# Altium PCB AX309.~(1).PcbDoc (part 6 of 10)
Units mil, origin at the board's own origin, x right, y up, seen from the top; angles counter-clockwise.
Board outline 5185 x 3614 mil, 4 copper layers (Top Layer, GND, Mid-Layer 1, Bottom Layer); 191 components, 352 nets, 1106 pads, 425 vias.
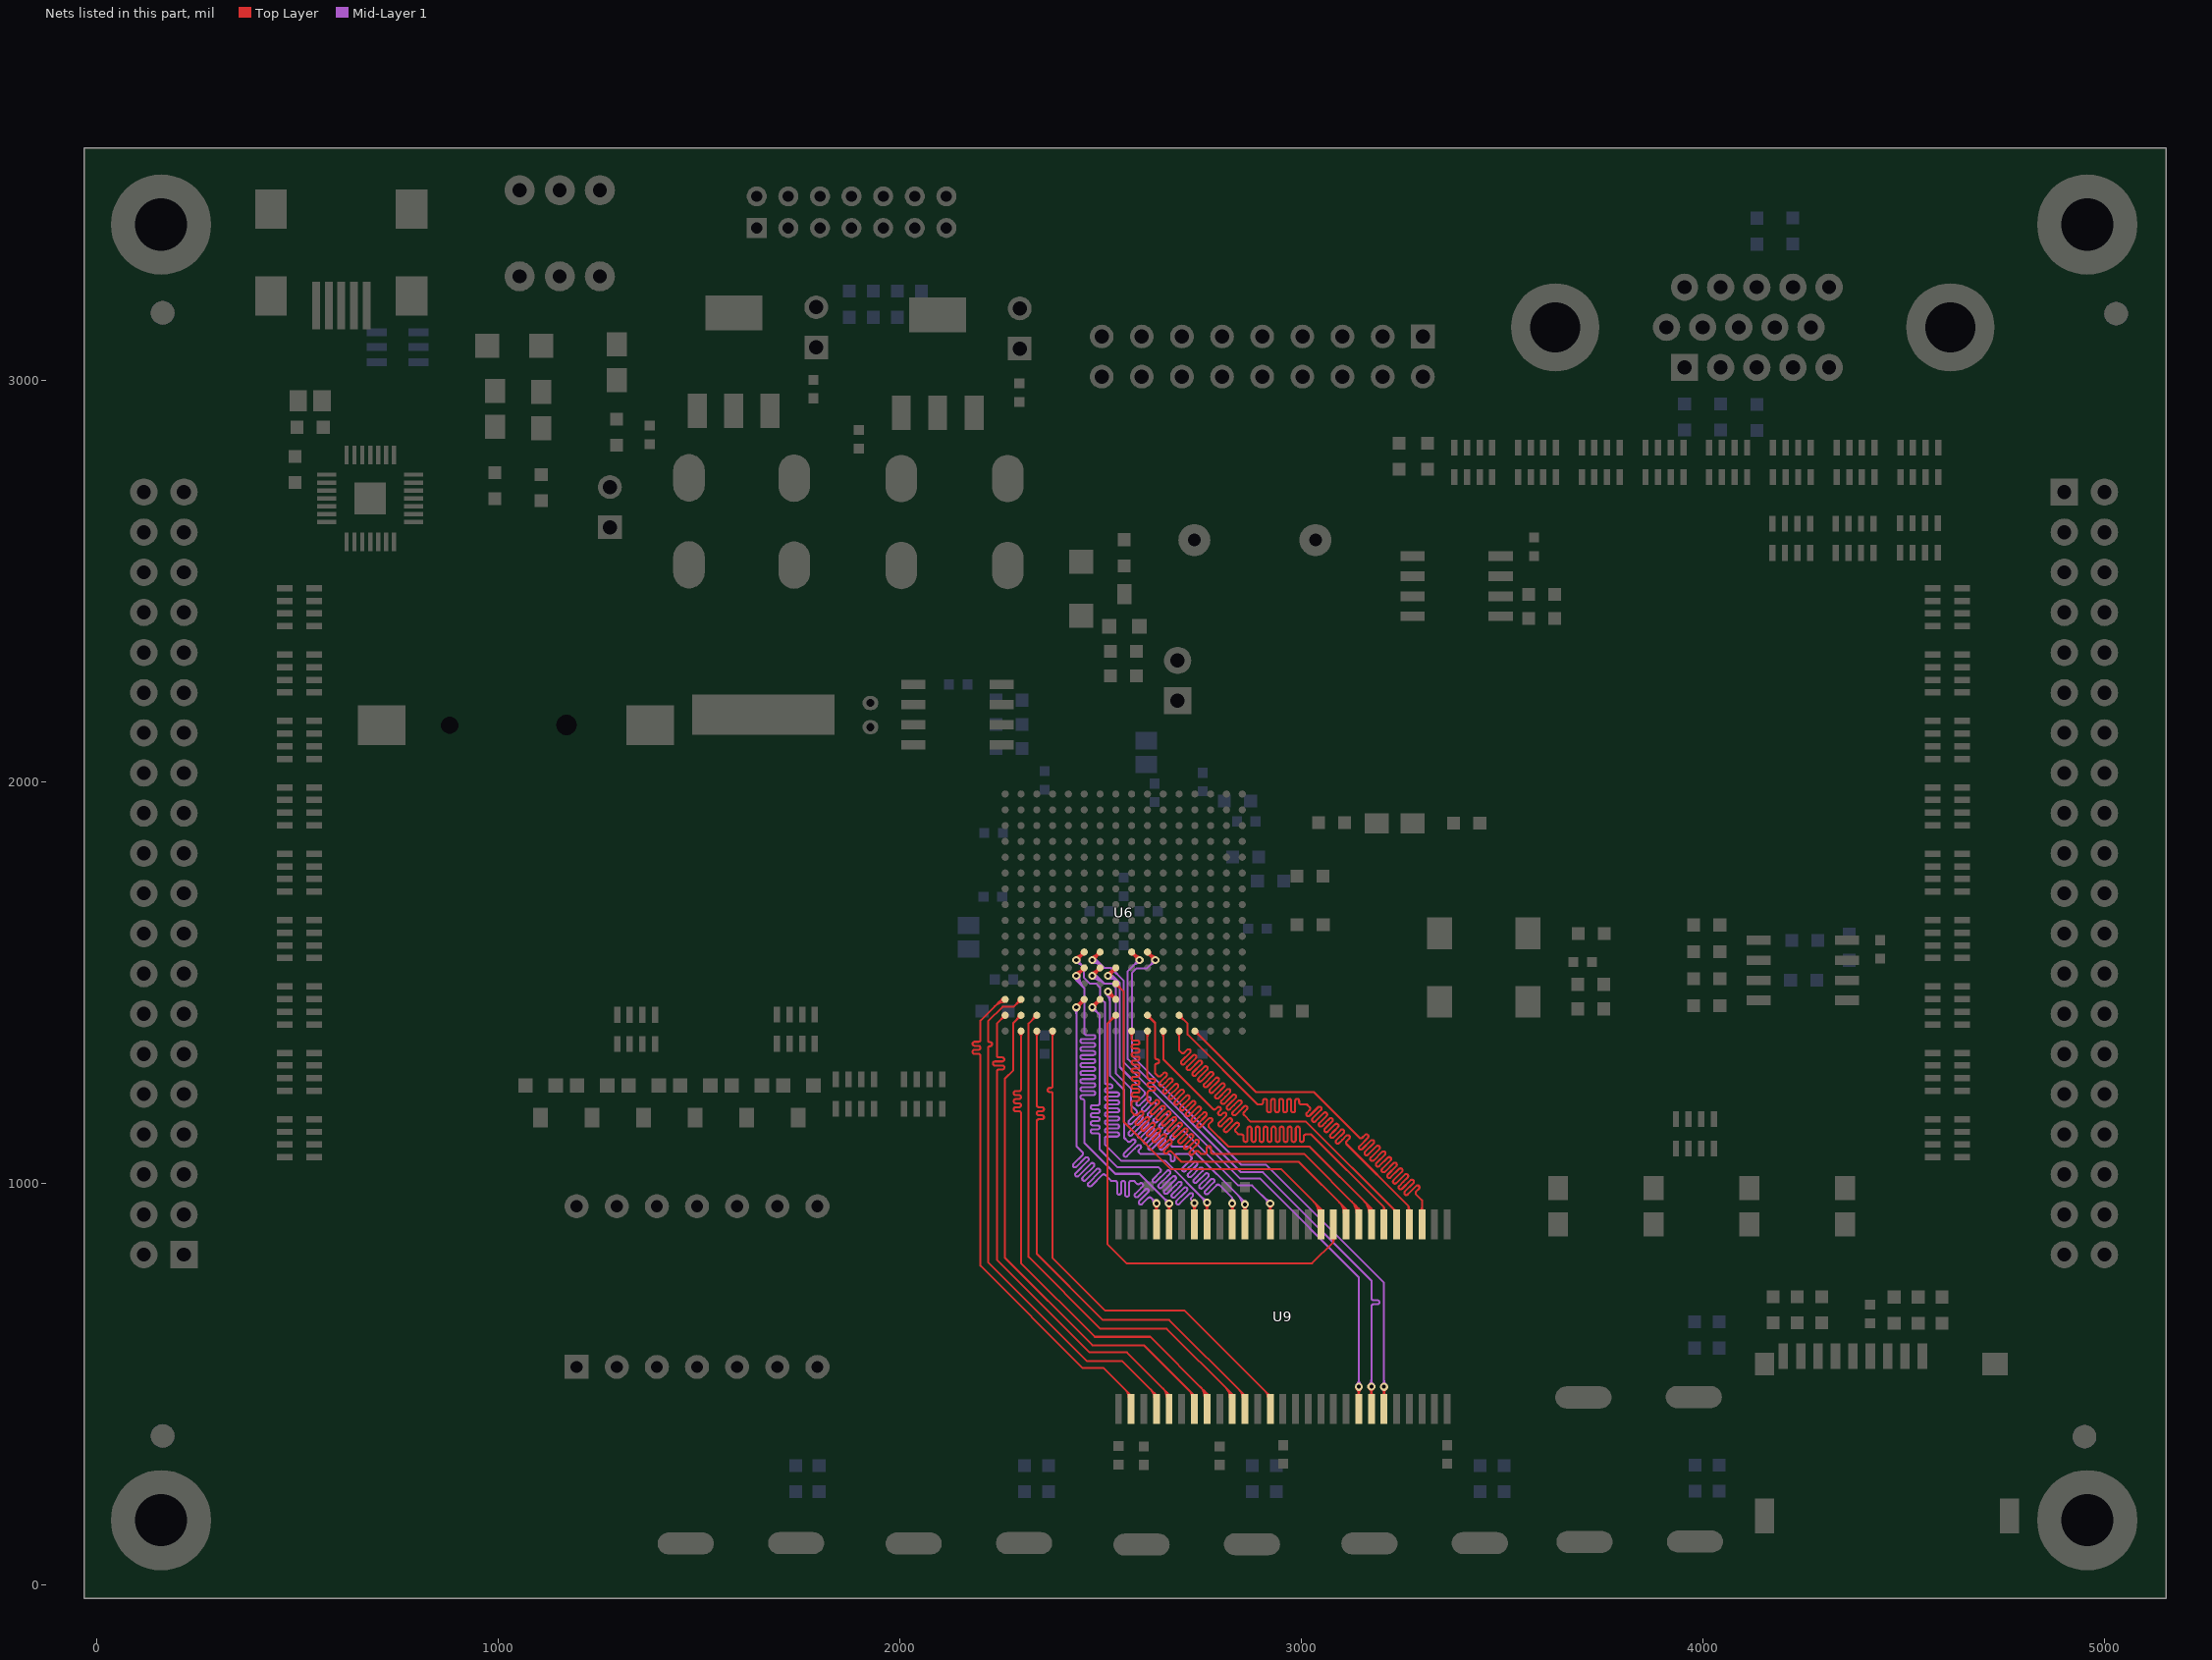
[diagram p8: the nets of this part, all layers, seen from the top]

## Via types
v1: diameter 20, hole 10, Top Layer to Bottom Layer, 328 vias
v2: diameter 30, hole 15, Top Layer to Bottom Layer, 95 vias
v3: diameter 40, hole 20, Top Layer to Bottom Layer, 2 vias

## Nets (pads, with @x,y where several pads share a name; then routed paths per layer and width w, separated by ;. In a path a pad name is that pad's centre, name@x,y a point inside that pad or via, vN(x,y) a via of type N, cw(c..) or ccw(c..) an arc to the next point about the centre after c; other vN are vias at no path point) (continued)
S_A5: U6.N1 U9.30 | length 1517.2
  Top Layer w5: U6.N1@2735.17,1372.37 cw(c2735.17,1357.02) 2746.02,1367.87 cw(c2756.87,1378.72) U6.N1@2741.52,1378.72 ; U6.N1@2735.17,1378.72 2886.89,1227 3031,1227 3145,1113 ccw(c3148.54,1116.54) 3152.07,1113 3159.06,1119.99 cw(c3162.6,1116.46) 3166.13,1119.99 cw(c3162.6,1116.46) 3166.13,1112.92 3145.08,1091.87 ccw(c3148.62,1088.33) 3145.08,1084.8 ccw(c3148.62,1088.33) 3152.15,1084.8 3173.2,1105.85 cw(c3176.74,1102.31) 3180.28,1105.85 cw(c3176.74,1102.31) 3180.28,1098.78 3159.22,1077.72 ccw(c3162.76,1074.19) 3159.22,1070.65 ccw(c3162.76,1074.19) 3166.29,1070.65 3187.35,1091.71 cw(c3190.88,1088.17) 3194.42,1091.71 cw(c3190.88,1088.17) 3194.42,1084.64 3173.36,1063.58 ccw(c3176.9,1060.05) 3173.36,1056.51 ccw(c3176.9,1060.05) 3180.43,1056.51 3201.49,1077.57 cw(c3205.02,1074.03) 3208.56,1077.57 cw(c3205.02,1074.03) 3208.56,1070.49 3187.51,1049.44 ccw(c3191.04,1045.9) 3187.51,1042.37 ccw(c3191.04,1045.9) 3194.58,1042.37 3215.63,1063.42 cw(c3219.17,1059.89) 3222.7,1063.42 cw(c3219.17,1059.89) 3222.7,1056.35 3201.65,1035.3 ccw(c3205.18,1031.76) 3201.65,1028.23 ccw(c3205.18,1031.76) 3208.72,1028.23 3229.77,1049.28 cw(c3233.31,1045.75) 3236.84,1049.28 cw(c3233.31,1045.75) 3236.84,1042.21 3215.79,1021.16 ccw(c3219.33,1017.62) 3215.79,1014.08 ccw(c3219.33,1017.62) 3222.86,1014.08 3243.92,1035.14 cw(c3247.45,1031.6) 3250.99,1035.14 cw(c3247.45,1031.6) 3250.99,1028.07 3229.93,1007.01 ccw(c3233.47,1003.48) 3229.93,999.94 ccw(c3233.47,1003.48) 3237,999.94 3258.06,1021 cw(c3261.59,1017.46) 3265.13,1021 cw(c3261.59,1017.46) 3265.13,1013.93 3254.6,1003.4 3244.07,992.87 ccw(c3247.61,989.34) 3244.07,985.8 ccw(c3247.61,989.34) 3251.15,985.8 3272.2,1006.85 cw(c3275.74,1003.32) 3279.27,1006.85 cw(c3275.74,1003.32) 3279.27,999.78 3258.22,978.73 ccw(c3261.75,975.19) 3258.22,971.66 ccw(c3261.75,975.19) 3265.29,971.66 3286.34,992.71 cw(c3289.88,989.18) 3293.41,992.71 cw(c3289.88,989.18) 3293.41,985.64 3286.42,978.65 ccw(c3289.96,975.11) 3286.42,971.58 3300.91,957.09 U9.30@3300.91,897 ; U9.30@3296.66,930.24 ccw(c3286.42,940.49) 3300.91,940.49 ccw(c3315.39,940.49) U9.30@3305.15,930.24
S_A6: U6.M2 U9.31 | length 1514.3
  Top Layer w5: U6.M2@2695.8,1411.74 cw(c2695.8,1396.39) 2706.65,1407.24 cw(c2717.5,1418.09) U6.M2@2702.15,1418.09 ; U6.M2@2695.8,1418.09 2717,1396.89 2717,1370 2891,1196 2900,1196 ccw(c2900,1201) 2905,1201 2905,1204.8 cw(c2910,1204.8) 2910,1209.8 cw(c2910,1204.8) 2915,1204.8 2915,1181.2 ccw(c2920,1181.2) 2920,1176.2 ccw(c2920,1181.2) 2925,1181.2 2925,1204.8 cw(c2930,1204.8) 2930,1209.8 cw(c2930,1204.8) 2935,1204.8 2935,1181.2 ccw(c2940,1181.2) 2940,1176.2 ccw(c2940,1181.2) 2945,1181.2 2945,1204.8 cw(c2950,1204.8) 2950,1209.8 cw(c2950,1204.8) 2955,1204.8 2955,1181.2 ccw(c2960,1181.2) 2960,1176.2 ccw(c2960,1181.2) 2965,1181.2 2965,1204.8 cw(c2970,1204.8) 2970,1209.8 cw(c2970,1204.8) 2975,1204.8 2975,1181.2 ccw(c2980,1181.2) 2980,1176.2 ccw(c2980,1181.2) 2985,1181.2 2985,1204.8 cw(c2990,1204.8) 2990,1209.8 cw(c2990,1204.8) 2995,1204.8 2995,1201 ccw(c3000,1201) 3000,1196 3014,1196 3021.07,1188.93 cw(c3017.54,1185.39) 3021.07,1181.86 3014.14,1174.93 ccw(c3017.68,1171.39) 3014.14,1167.86 ccw(c3017.68,1171.39) 3021.21,1167.86 3042.14,1188.79 cw(c3045.68,1185.25) 3049.22,1188.79 cw(c3045.68,1185.25) 3049.22,1181.72 3028.28,1160.78 ccw(c3031.82,1157.25) 3028.28,1153.71 ccw(c3031.82,1157.25) 3035.35,1153.71 3056.29,1174.65 cw(c3059.82,1171.11) 3063.36,1174.65 cw(c3059.82,1171.11) 3063.36,1167.58 3045.14,1149.35 ccw(c3048.67,1145.82) 3045.14,1142.28 ccw(c3048.67,1145.82) 3052.21,1142.28 3059.96,1150.04 3070.43,1160.51 cw(c3073.96,1156.97) 3077.5,1160.5 cw(c3073.96,1156.97) 3077.5,1153.43 3059.28,1135.21 ccw(c3062.81,1131.68) 3059.28,1128.14 ccw(c3062.81,1131.68) 3066.35,1128.14 3084.57,1146.36 cw(c3088.11,1142.83) 3091.64,1146.36 cw(c3088.11,1142.83) 3091.64,1139.29 3081.18,1128.82 3073.42,1121.07 ccw(c3076.96,1117.53) 3073.42,1114 ccw(c3076.96,1117.53) 3080.49,1114 3098.71,1132.22 cw(c3102.25,1128.69) 3105.78,1132.22 cw(c3102.25,1128.69) 3105.78,1125.15 3087.56,1106.93 ccw(c3091.1,1103.39) 3087.56,1099.86 ccw(c3091.1,1103.39) 3094.63,1099.86 3102.39,1107.61 3112.86,1118.08 cw(c3116.39,1114.54) 3119.93,1118.08 cw(c3116.39,1114.54) 3119.93,1111.01 3112.99,1104.08 ccw(c3116.53,1100.54) 3112.99,1097.01 3267.5,942.5 ; U9.31@3265.17,930.24 ccw(c3259.53,935.88) 3267.5,935.88 ; U9.31@3267.5,898.91 3267.5,942.5 ; U9.31@3273.17,930.68 cw(c3282.66,942.5) 3267.5,942.5
S_A7: U6.M1 U9.32 | length 1542
  Top Layer w5: U6.M1@2691.3,1374.23 cw(c2680.45,1363.37) 2695.8,1363.37 cw(c2711.15,1363.37) U6.M1@2700.29,1374.23 ; U6.M1@2695.8,1378.72 2695.8,1331.2 2702,1325 ccw(c2705.54,1328.54) 2709.07,1325 2716.1,1332.03 cw(c2719.64,1328.5) 2723.17,1332.03 cw(c2719.64,1328.5) 2723.17,1324.96 2702.04,1303.83 ccw(c2705.57,1300.29) 2702.04,1296.75 ccw(c2705.57,1300.29) 2709.11,1296.75 2730.25,1317.89 cw(c2733.78,1314.35) 2737.32,1317.89 cw(c2733.78,1314.35) 2737.32,1310.82 2716.18,1289.68 ccw(c2719.72,1286.15) 2716.18,1282.61 ccw(c2719.72,1286.15) 2723.25,1282.61 2744.39,1303.75 cw(c2747.92,1300.21) 2751.46,1303.75 cw(c2747.92,1300.21) 2751.46,1296.68 2730.32,1275.54 ccw(c2733.86,1272.01) 2730.32,1268.47 ccw(c2733.86,1272.01) 2737.39,1268.47 2758.53,1289.61 cw(c2762.06,1286.07) 2765.6,1289.61 cw(c2762.06,1286.07) 2765.6,1282.53 2744.47,1261.4 ccw(c2748,1257.86) 2744.47,1254.33 ccw(c2748,1257.86) 2751.54,1254.33 2772.67,1275.46 cw(c2776.21,1271.93) 2779.74,1275.46 cw(c2776.21,1271.93) 2779.74,1268.39 2758.61,1247.26 ccw(c2762.14,1243.72) 2758.61,1240.19 ccw(c2762.14,1243.72) 2765.68,1240.19 2786.81,1261.32 cw(c2790.35,1257.79) 2793.88,1261.32 cw(c2790.35,1257.79) 2793.88,1254.25 2772.75,1233.12 ccw(c2776.29,1229.58) 2772.75,1226.04 ccw(c2776.29,1229.58) 2779.82,1226.04 2800.96,1247.18 cw(c2804.49,1243.64) 2808.03,1247.18 cw(c2804.49,1243.64) 2808.03,1240.11 2786.89,1218.97 ccw(c2790.43,1215.44) 2786.89,1211.9 ccw(c2790.43,1215.44) 2793.96,1211.9 2815.1,1233.04 cw(c2818.63,1229.5) 2822.17,1233.04 cw(c2818.63,1229.5) 2822.17,1225.97 2811.6,1215.4 2801.64,1205.43 ccw(c2805.17,1201.9) 2801.64,1198.36 ccw(c2805.17,1201.9) 2808.71,1198.36 2818.67,1208.33 2829.24,1218.89 cw(c2832.78,1215.36) 2836.31,1218.89 cw(c2832.78,1215.36) 2836.31,1211.82 2825.74,1201.26 2815.78,1191.29 ccw(c2819.32,1187.76) 2815.78,1184.22 ccw(c2819.32,1187.76) 2822.85,1184.22 2832.81,1194.19 2843.38,1204.75 cw(c2846.92,1201.22) 2850.45,1204.75 cw(c2846.92,1201.22) 2850.45,1197.68 2839.89,1187.11 2829.92,1177.15 ccw(c2833.46,1173.61) 2829.92,1170.08 ccw(c2833.46,1173.61) 2836.99,1170.08 2846.96,1180.04 2857.52,1190.61 cw(c2861.06,1187.07) 2864.6,1190.61 cw(c2861.06,1187.07) 2864.6,1183.54 2857.56,1176.51 ccw(c2861.1,1172.97) 2857.56,1169.44 2874,1153 3012,1153 U9.32@3237.91,927.09 ; 3226.9,938.1 cw(c3214.8,926) U9.32@3231.91,926 ; 3229.53,935.47 ccw(c3237.91,943.86) U9.32@3237.91,932
S_A8: U6.L1 U9.33 | length 1539.8
  Top Layer w5: U6.L1@2651.93,1374.23 cw(c2641.08,1363.37) 2656.43,1363.37 cw(c2671.78,1363.37) U6.L1@2660.92,1374.23 ; U6.L1@2656.43,1378.72 2656.43,1308.57 2780.36,1184.64 ccw(c2783.9,1188.18) 2787.43,1184.64 2791.14,1188.35 cw(c2794.68,1184.81) 2798.21,1188.35 cw(c2794.68,1184.81) 2798.21,1181.28 2794.5,1177.57 ccw(c2798.04,1174.03) 2794.5,1170.5 ccw(c2798.04,1174.03) 2801.57,1170.5 2805.28,1174.21 cw(c2808.82,1170.67) 2812.35,1174.21 cw(c2808.82,1170.67) 2812.35,1167.14 2805.11,1159.89 2794.76,1149.54 ccw(c2798.29,1146) 2794.76,1142.47 ccw(c2798.29,1146) 2801.83,1142.47 2819.43,1160.06 cw(c2822.96,1156.53) 2826.5,1160.06 cw(c2822.96,1156.53) 2826.5,1152.99 2819.25,1145.75 2808.9,1135.4 ccw(c2812.43,1131.86) 2808.9,1128.32 ccw(c2812.43,1131.86) 2815.97,1128.32 2836.68,1149.03 cw(c2840.21,1145.5) 2843.75,1149.03 cw(c2840.21,1145.5) 2843.75,1141.96 2836.93,1135.14 ccw(c2840.46,1131.61) 2836.93,1128.07 2844,1121 2851.39,1121 cw(c2851.39,1116) 2856.39,1116 2856.39,1107.36 ccw(c2861.39,1107.36) 2861.39,1102.36 ccw(c2861.39,1107.36) 2866.39,1107.36 2866.39,1135.64 cw(c2871.39,1135.64) 2871.39,1140.64 cw(c2871.39,1135.64) 2876.39,1135.64 2876.39,1107.36 ccw(c2881.39,1107.36) 2881.39,1102.36 ccw(c2881.39,1107.36) 2886.39,1107.36 2886.39,1135.64 cw(c2891.39,1135.64) 2891.39,1140.64 cw(c2891.39,1135.64) 2896.39,1135.64 2896.39,1107.36 ccw(c2901.39,1107.36) 2901.39,1102.36 ccw(c2901.39,1107.36) 2906.39,1107.36 2906.39,1135.64 cw(c2911.39,1135.64) 2911.39,1140.64 cw(c2911.39,1135.64) 2916.39,1135.64 2916.39,1107.36 ccw(c2921.39,1107.36) 2921.39,1102.36 ccw(c2921.39,1107.36) 2926.39,1107.36 2926.39,1135.64 cw(c2931.39,1135.64) 2931.39,1140.64 cw(c2931.39,1135.64) 2936.39,1135.64 2936.39,1107.36 ccw(c2941.39,1107.36) 2941.39,1102.36 ccw(c2941.39,1107.36) 2946.39,1107.36 2946.39,1135.64 cw(c2951.39,1135.64) 2951.39,1140.64 cw(c2951.39,1135.64) 2956.39,1135.64 2956.39,1107.36 ccw(c2961.39,1107.36) 2961.39,1102.36 ccw(c2961.39,1107.36) 2966.39,1107.36 2966.39,1135.64 cw(c2971.39,1135.64) 2971.39,1140.64 cw(c2971.39,1135.64) 2976.39,1135.64 2976.39,1107.36 ccw(c2981.39,1107.36) 2981.39,1102.36 ccw(c2981.39,1107.36) 2986.39,1107.36 2986.39,1135.64 cw(c2991.39,1135.64) 2991.39,1140.64 cw(c2991.39,1135.64) 2996.39,1135.64 2996.39,1107.36 ccw(c3001.39,1107.36) 3001.39,1102.36 ccw(c3001.39,1107.36) 3006.39,1107.36 3006.39,1116 cw(c3011.39,1116) 3011.39,1121 3025,1121 3206.42,939.58 ; U9.33@3202.38,930.44 ccw(c3194.04,939.58) 3206.42,939.58 ; U9.33@3206.42,897 3206.42,939.58 ; U9.33@3210.46,930.44 cw(c3218.79,939.58) 3206.42,939.58
S_A9: U6.K2 U9.34 | length 1576.9
  Top Layer w5: U6.K2@2617.06,1411.74 cw(c2617.06,1396.39) 2627.91,1407.24 cw(c2638.76,1418.09) U6.K2@2623.41,1418.09 ; U6.K2@2617.06,1418.09 2636,1399.15 2636,1313 ccw(c2641,1313) 2641,1308 2641.33,1308 cw(c2641.33,1303) 2646.33,1303 cw(c2641.33,1303) 2641.33,1298 2641,1298 ccw(c2641,1293) 2636,1293 2636,1274 2643.07,1266.93 ccw(c2646.61,1270.46) 2650.14,1266.93 2657.14,1273.93 cw(c2660.68,1270.39) 2664.21,1273.93 cw(c2660.68,1270.39) 2664.21,1266.86 2653.68,1256.32 2647.22,1249.87 ccw(c2650.76,1246.33) 2647.22,1242.8 ccw(c2650.76,1246.33) 2654.3,1242.8 2660.75,1249.25 2671.28,1259.79 cw(c2674.82,1256.25) 2678.35,1259.79 cw(c2674.82,1256.25) 2678.35,1252.72 2657.28,1231.65 ccw(c2660.82,1228.11) 2657.28,1224.57 ccw(c2660.82,1228.11) 2664.36,1224.57 2685.43,1245.64 cw(c2688.96,1242.11) 2692.5,1245.64 cw(c2688.96,1242.11) 2692.5,1238.57 2671.43,1217.5 ccw(c2674.96,1213.97) 2671.43,1210.43 ccw(c2674.96,1213.97) 2678.5,1210.43 2699.57,1231.5 cw(c2703.1,1227.97) 2706.64,1231.5 cw(c2703.1,1227.97) 2706.64,1224.43 2685.57,1203.36 ccw(c2689.1,1199.83) 2685.57,1196.29 ccw(c2689.1,1199.83) 2692.64,1196.29 2713.71,1217.36 cw(c2717.25,1213.82) 2720.78,1217.36 cw(c2717.25,1213.82) 2720.78,1210.29 2699.71,1189.22 ccw(c2703.25,1185.68) 2699.71,1182.15 ccw(c2703.25,1185.68) 2706.78,1182.15 2727.85,1203.22 cw(c2731.39,1199.68) 2734.92,1203.22 cw(c2731.39,1199.68) 2734.92,1196.15 2713.85,1175.08 ccw(c2717.39,1171.54) 2713.85,1168.01 ccw(c2717.39,1171.54) 2720.92,1168.01 2741.99,1189.08 cw(c2745.53,1185.54) 2749.07,1189.08 cw(c2745.53,1185.54) 2749.07,1182 2728,1160.93 ccw(c2731.53,1157.4) 2728,1153.86 ccw(c2731.53,1157.4) 2735.07,1153.86 2745.6,1164.4 2756.14,1174.93 cw(c2759.67,1171.4) 2763.21,1174.93 cw(c2759.67,1171.4) 2763.21,1167.86 2742.14,1146.79 ccw(c2745.67,1143.26) 2742.14,1139.72 ccw(c2745.67,1143.26) 2749.21,1139.72 2770.28,1160.79 cw(c2773.81,1157.26) 2777.35,1160.79 cw(c2773.81,1157.26) 2777.35,1153.72 2770.35,1146.72 ccw(c2773.89,1143.19) 2770.35,1139.65 2819,1091 3021,1091 3175,937 ; 3156.98,955.02 cw(c3127.96,926) U9.34@3169,926 ; 3165.51,946.49 cw(c3145.03,926) U9.34@3174,926 ; U9.34@3171.75,931.04 ccw(c3167.92,937) 3175,937 ; 3174.05,937.95 cw(c3162.1,926) U9.34@3179,926 ; U9.34@3175,897 3175,937 ; U9.34@3178.25,931.04 cw(c3182.08,937) 3175,937
S_A10: U6.K6 U9.22 | length 1742.1
  Top Layer w5: U6.K6@2617.06,1569.22 cw(c2617.06,1553.87) 2627.91,1564.72 cw(c2638.76,1575.57) U6.K6@2623.41,1575.57 ; U6.K6@2617.06,1575.57 v1(2636.74,1555.89) ; U6.K6@2619.41,1569.63 cw(c2609.33,1552.17) v1@2629.31,1554.88 ; U6.K6@2623,1573.22 ccw(c2640.46,1583.3) v1@2637.75,1563.32 ; 2626.29,1565.65 cw(c2622.84,1559.67) v1@2629.5,1557.86 ; 2626.98,1566.34 ccw(c2632.96,1569.79) v1@2634.77,1563.13 ; 2628.1,1564.39 ccw(c2638.73,1570.53) v1@2637.08,1558.37 ; 2628.24,1564.53 cw(c2622.1,1553.9) v1@2634.26,1555.55 ; v1@2629.24,1555.89 ccw(c2611.13,1555.89) 2623.94,1568.69 ccw(c2636.74,1581.5) v1@2636.74,1563.39 ; v1@3201.11,487.11 cw(c3188.31,474.31) 3206.42,474.31 cw(c3224.52,474.31) v1@3211.72,487.11 ; U9.22@3202.17,470.24 ccw(c3191.93,480.49) 3206.42,480.49 ccw(c3220.9,480.49) U9.22@3210.66,470.24 ; U9.22@3206.42,437 v1(3206.42,492.42) ; v1@2629.5,1557.83 ccw(c2622.67,1559.66) 2628.79,1563.19 cw(c2622.67,1559.66) v1@2629.5,1557.83 ; 2629.44,1563.84 ccw(c2632.97,1569.96) 2634.8,1563.13 cw(c2632.97,1569.96) 2629.44,1563.84
  Mid-Layer 1 w5: v1@2629.24,1555.89 cw(c2611.13,1555.89) 2623.94,1543.09 cw(c2636.74,1530.28) v1@2636.74,1548.39 ; v1(2636.74,1555.89) 2615.85,1535 2590,1535 2579,1524 2579,1317 2850,1046 2912,1046 3206.42,751.58 v1(3206.42,492.42) ; v1@3201.11,497.72 ccw(c3188.31,510.52) 3206.42,510.52 ccw(c3224.52,510.52) v1@3211.72,497.72
S_A11: U6.K1 U9.35 | length 1573.4
  Top Layer w5: U6.K1@2612.56,1374.23 cw(c2601.7,1363.37) 2617.06,1363.37 cw(c2632.41,1363.37) U6.K1@2621.55,1374.23 ; U6.K1@2617.06,1378.72 2617.06,1265 ccw(c2622.06,1265) 2622.06,1260 2631.59,1260 cw(c2631.59,1255) 2636.59,1255 cw(c2631.59,1255) 2631.59,1250 2622.06,1250 ccw(c2622.06,1245) 2617.06,1245 ccw(c2622.06,1245) 2622.06,1240 2631.59,1240 cw(c2631.59,1235) 2636.59,1235 cw(c2631.59,1235) 2631.59,1230 2622.06,1230 ccw(c2622.06,1225) 2617.06,1225 2617.06,1205.94 2624.13,1198.87 ccw(c2627.66,1202.41) 2631.2,1198.87 2637.94,1205.62 cw(c2641.48,1202.08) 2645.01,1205.62 cw(c2641.48,1202.08) 2645.01,1198.55 2634.73,1188.27 2626.13,1179.66 ccw(c2629.66,1176.13) 2626.13,1172.59 ccw(c2629.66,1176.13) 2633.2,1172.59 2641.8,1181.2 2652.08,1191.48 cw(c2655.62,1187.94) 2659.16,1191.48 cw(c2655.62,1187.94) 2659.16,1184.41 2640.27,1165.52 ccw(c2643.81,1161.99) 2640.27,1158.45 ccw(c2643.81,1161.99) 2647.34,1158.45 2655.95,1167.05 2666.23,1177.33 cw(c2669.76,1173.8) 2673.3,1177.33 cw(c2669.76,1173.8) 2673.3,1170.26 2663.02,1159.98 2654.41,1151.38 ccw(c2657.95,1147.84) 2654.41,1144.31 ccw(c2657.95,1147.84) 2661.48,1144.31 2670.09,1152.91 2680.37,1163.19 cw(c2683.9,1159.66) 2687.44,1163.19 cw(c2683.9,1159.66) 2687.44,1156.12 2677.16,1145.84 2668.56,1137.24 ccw(c2672.09,1133.7) 2668.56,1130.17 ccw(c2672.09,1133.7) 2675.63,1130.17 2684.23,1138.77 2694.51,1149.05 cw(c2698.05,1145.52) 2701.58,1149.05 cw(c2698.05,1145.52) 2701.58,1141.98 2691.3,1131.7 2682.7,1123.09 ccw(c2686.23,1119.56) 2682.7,1116.02 ccw(c2686.23,1119.56) 2689.77,1116.02 2698.37,1124.63 2708.65,1134.91 cw(c2712.19,1131.37) 2715.72,1134.91 cw(c2712.19,1131.37) 2715.72,1127.84 2695.16,1107.28 ccw(c2698.7,1103.74) 2695.16,1100.2 ccw(c2698.7,1103.74) 2702.23,1100.2 2722.8,1120.77 cw(c2726.33,1117.23) 2729.87,1120.77 cw(c2726.33,1117.23) 2729.87,1113.7 2709.3,1093.13 ccw(c2712.84,1089.6) 2709.3,1086.06 ccw(c2712.84,1089.6) 2716.38,1086.06 2726.66,1096.34 2736.94,1106.62 cw(c2740.47,1103.09) 2744.01,1106.62 cw(c2740.47,1103.09) 2744.01,1099.55 2723.45,1078.99 ccw(c2726.98,1075.46) 2723.45,1071.92 ccw(c2726.98,1075.46) 2730.52,1071.92 2737.26,1078.67 cw(c2740.8,1075.13) 2744.33,1078.67 2750,1073 2760,1073 ccw(c2760,1078) 2765,1078 2765,1087.54 cw(c2770,1087.54) 2770,1092.54 cw(c2770,1087.54) 2775,1087.54 2775,1078 ccw(c2780,1078) 2780,1073 3007,1073 3143.43,936.57 ; 3125.71,954.29 cw(c3097.41,926) U9.35@3137.43,926 ; 3134.24,945.76 cw(c3114.48,926) U9.35@3142.43,926 ; U9.35@3140.35,931.15 ccw(c3137.11,936.57) 3143.43,936.57 ; 3142.78,937.22 cw(c3131.55,926) U9.35@3147.43,926 ; U9.35@3143.43,897 3143.43,936.57 ; U9.35@3146.5,931.15 cw(c3149.74,936.57) 3143.43,936.57
S_A12: U6.J1 U9.36 | length 1560.2
  Top Layer w5: U6.J1@2573.19,1374.23 cw(c2562.33,1363.37) 2577.68,1363.37 cw(c2593.04,1363.37) U6.J1@2582.18,1374.23 ; U6.J1@2577.68,1378.72 2577.68,1360 ccw(c2582.68,1360) 2582.68,1355 2592.28,1355 cw(c2592.28,1350) 2597.28,1350 cw(c2592.28,1350) 2592.28,1345 2582.68,1345 ccw(c2582.68,1340) 2577.68,1340 ccw(c2582.68,1340) 2582.68,1335 2592.28,1335 cw(c2592.28,1330) 2597.28,1330 cw(c2592.28,1330) 2592.28,1325 2582.68,1325 ccw(c2582.68,1320) 2577.68,1320 ccw(c2582.68,1320) 2582.68,1315 2592.28,1315 cw(c2592.28,1310) 2597.28,1310 cw(c2592.28,1310) 2592.28,1305 2582.68,1305 ccw(c2582.68,1300) 2577.68,1300 ccw(c2582.68,1300) 2582.68,1295 2592.28,1295 cw(c2592.28,1290) 2597.28,1290 cw(c2592.28,1290) 2592.28,1285 2582.68,1285 ccw(c2582.68,1280) 2577.68,1280 ccw(c2582.68,1280) 2582.68,1275 2592.28,1275 cw(c2592.28,1270) 2597.28,1270 cw(c2592.28,1270) 2592.28,1265 2582.68,1265 ccw(c2582.68,1260) 2577.68,1260 ccw(c2582.68,1260) 2582.68,1255 2592.28,1255 cw(c2592.28,1250) 2597.28,1250 cw(c2592.28,1250) 2592.28,1245 2582.68,1245 ccw(c2582.68,1240) 2577.68,1240 ccw(c2582.68,1240) 2582.68,1235 2592.28,1235 cw(c2592.28,1230) 2597.28,1230 cw(c2592.28,1230) 2592.28,1225 2582.68,1225 ccw(c2582.68,1220) 2577.68,1220 ccw(c2582.68,1220) 2582.68,1215 2592.28,1215 cw(c2592.28,1210) 2597.28,1210 cw(c2592.28,1210) 2592.28,1205 2582.68,1205 ccw(c2582.68,1200) 2577.68,1200 2577.68,1177.32 2584.76,1170.24 ccw(c2588.29,1173.78) 2591.83,1170.24 2598.61,1177.03 cw(c2602.15,1173.49) 2605.68,1177.03 cw(c2602.15,1173.49) 2605.68,1169.96 2595.36,1159.64 2588.75,1153.03 ccw(c2592.29,1149.49) 2588.75,1145.96 ccw(c2592.29,1149.49) 2595.83,1145.96 2602.43,1152.57 2612.75,1162.89 cw(c2616.29,1159.35) 2619.83,1162.89 cw(c2616.29,1159.35) 2619.83,1155.82 2602.9,1138.89 ccw(c2606.43,1135.35) 2602.9,1131.82 ccw(c2606.43,1135.35) 2609.97,1131.82 2616.58,1138.42 2626.9,1148.74 cw(c2630.43,1145.21) 2633.97,1148.74 cw(c2630.43,1145.21) 2633.97,1141.67 2623.65,1131.35 2617.04,1124.74 ccw(c2620.57,1121.21) 2617.04,1117.67 ccw(c2620.57,1121.21) 2624.11,1117.67 2641.04,1134.6 cw(c2644.57,1131.07) 2648.11,1134.6 cw(c2644.57,1131.07) 2648.11,1127.53 2637.79,1117.21 2631.18,1110.6 ccw(c2634.72,1107.07) 2631.18,1103.53 ccw(c2634.72,1107.07) 2638.25,1103.53 2644.86,1110.14 2655.18,1120.46 cw(c2658.72,1116.92) 2662.25,1120.46 cw(c2658.72,1116.92) 2662.25,1113.39 2645.32,1096.46 ccw(c2648.86,1092.92) 2645.32,1089.39 ccw(c2648.86,1092.92) 2652.39,1089.39 2659,1096 2669.32,1106.32 cw(c2672.86,1102.78) 2676.39,1106.32 cw(c2672.86,1102.78) 2676.39,1099.25 2666.07,1088.93 2659.47,1082.32 ccw(c2663,1078.78) 2659.47,1075.25 ccw(c2663,1078.78) 2666.54,1075.25 2669.61,1078.32 cw(c2673.14,1074.78) 2676.68,1078.32 2702,1053 2993.93,1053 3111.93,935 ; 3095.32,951.61 cw(c3069.72,926) U9.36@3105.93,926 ; 3103.86,943.07 cw(c3086.79,926) U9.36@3110.93,926 ; U9.36@3109.62,931.54 ccw(c3108.18,935) 3111.93,935 ; U9.36@3111.93,897 3111.93,935 ; 3112.39,934.54 cw(c3103.86,926) U9.36@3115.93,926 ; U9.36@3114.24,931.54 cw(c3115.68,935) 3111.93,935
S_BA0: U6.G6 U9.20 | length 1782.8
  Top Layer w5: v1@2478.25,1563.32 ccw(c2475.54,1583.3) U6.G6@2493,1573.22 ; v1@2478.92,1558.37 ccw(c2477.27,1570.53) 2487.9,1564.39 ; v1(2479.26,1555.89) U6.G6@2498.94,1575.57 ; v1@2479.26,1563.39 ccw(c2479.26,1581.5) 2492.06,1568.69 ccw(c2504.87,1555.89) v1@2486.76,1555.89 ; v1@2481.23,1563.13 ccw(c2483.04,1569.79) 2489.02,1566.34 ; v1@2481.74,1555.55 cw(c2493.9,1553.9) 2487.76,1564.53 ; v1@2486.69,1554.88 cw(c2506.67,1552.17) U6.G6@2496.59,1569.63 ; 2489.71,1565.65 ccw(c2493.16,1559.67) v1@2486.5,1557.86 ; U6.G6@2492.59,1575.57 cw(c2477.24,1575.57) 2488.09,1564.72 cw(c2498.94,1553.87) U6.G6@2498.94,1569.22 ; v1@3138.12,487.12 cw(c3125.32,474.32) 3143.43,474.32 cw(c3161.53,474.32) v1@3148.73,487.12 ; U9.20@3139.18,470.24 ccw(c3128.94,480.49) 3143.43,480.49 ccw(c3157.91,480.49) U9.20@3147.67,470.24 ; U9.20@3143.43,437 v1(3143.43,492.43) ; v1@2486.5,1557.83 cw(c2493.33,1559.66) 2487.21,1563.19 ccw(c2493.33,1559.66) v1@2486.5,1557.83 ; v1@2481.2,1563.13 ccw(c2483.03,1569.96) 2486.56,1563.84 cw(c2483.03,1569.96) v1@2481.2,1563.13
  Mid-Layer 1 w5: v1@2479.22,1558.39 cw(c2479.54,1538.91) 2493.32,1552.68 ; v1(2479.26,1555.89) 2490.11,1555.89 ; v1@2479.3,1553.39 cw(c2479.81,1522.49) 2501.66,1544.34 ; v1@2479.38,1548.39 cw(c2480.08,1506.08) 2510,1536 ; v1@2486.27,1553.24 cw(c2490.11,1551.79) 2490.11,1555.89 ; v1@2486.27,1558.54 ccw(c2490.11,1559.99) 2490.11,1555.89 ; v1@3138.12,497.73 ccw(c3125.32,510.53) 3143.43,510.53 ccw(c3161.53,510.53) v1@3148.73,497.73 ; v1(3143.43,492.43) 3143.43,765.57 2898,1011 2848,1011 2558,1301 2558,1504 2526,1536 2510,1536 ; 2490.11,1555.89 2510,1536
S_BA1: U6.J6 U9.21 | length 1734.6
  Top Layer w5: U6.J6@2577.68,1569.22 cw(c2577.68,1553.87) 2588.54,1564.72 cw(c2599.39,1575.57) U6.J6@2584.04,1575.57 ; U6.J6@2577.68,1575.57 v1(2597.37,1555.89) ; U6.J6@2580.04,1569.63 cw(c2569.96,1552.17) v1@2589.94,1554.88 ; U6.J6@2583.63,1573.22 ccw(c2601.09,1583.3) v1@2598.38,1563.32 ; 2586.92,1565.65 cw(c2583.47,1559.67) v1@2590.13,1557.86 ; 2587.61,1566.34 ccw(c2593.59,1569.79) v1@2595.4,1563.13 ; 2588.73,1564.39 ccw(c2599.36,1570.53) v1@2597.71,1558.37 ; 2588.87,1564.53 cw(c2582.73,1553.9) v1@2594.89,1555.55 ; v1@2589.87,1555.89 ccw(c2571.76,1555.89) 2584.57,1568.69 ccw(c2597.37,1581.5) v1@2597.37,1563.39 ; v1@3169.62,487.62 cw(c3156.81,474.81) 3174.92,474.81 cw(c3193.03,474.81) v1@3180.22,487.62 ; U9.21@3170.68,470.24 ccw(c3160.44,480.49) 3174.92,480.49 ccw(c3189.41,480.49) U9.21@3179.16,470.24 ; U9.21@3174.92,437 v1(3174.92,492.92) ; v1@2590.13,1557.83 ccw(c2583.3,1559.66) 2589.42,1563.19 cw(c2583.3,1559.66) v1@2590.13,1557.83 ; 2590.07,1563.84 ccw(c2593.6,1569.96) 2595.43,1563.13 cw(c2593.6,1569.96) 2590.07,1563.84
  Mid-Layer 1 w5: 2582.04,1542.04 cw(c2597.37,1526.7) v1@2597.37,1548.39 ; 2585.62,1545.62 ccw(c2575.34,1555.89) v1@2589.87,1555.89 ; v1(2597.37,1555.89) 2595.89,1555.89 2568,1528 2568,1309 2850,1027 2905,1027 3174.92,757.08 3174.92,713 ccw(c3179.92,713) 3179.92,708 3189.76,708 cw(c3189.76,703) 3194.76,703 cw(c3189.76,703) 3189.76,698 3179.92,698 ccw(c3179.92,693) 3174.92,693 v1(3174.92,492.92) ; v1@3169.62,498.22 ccw(c3156.81,511.03) 3174.92,511.03 ccw(c3193.03,511.03) v1@3180.22,498.22
S_CKE: U6.H2 U9.37 | length 1274
  Top Layer w5: U6.H2@2531.96,1418.09 cw(c2516.61,1418.09) 2527.46,1407.24 cw(c2538.32,1396.39) U6.H2@2538.32,1411.74 ; U6.H2@2538.32,1418.09 2518,1397.78 2518,847 2565,800 3027,800 3080.43,853.43 U9.37@3080.43,897 ; U9.37@3076.19,863.76 cw(c3065.95,853.51) 3080.43,853.51 cw(c3094.92,853.51) U9.37@3084.68,863.76
S_CLK: U6.H4 U9.38 | length 1070.6
  Top Layer w5: U6.H4@2538.32,1490.48 cw(c2538.32,1475.13) 2549.17,1485.98 cw(c2560.02,1496.83) U6.H4@2544.67,1496.83 ; U6.H4@2538.32,1496.83 2558,1477.15 2558,1152 2675,1035 2949.94,1035 3048.94,936 ; 3031.62,953.31 cw(c3004.31,926) U9.38@3042.94,926 ; 3040.16,944.78 cw(c3021.38,926) U9.38@3047.94,926 ; U9.38@3046.11,931.29 ccw(c3043.6,936) 3048.94,936 ; 3048.69,936.24 cw(c3038.45,926) U9.38@3052.94,926 ; U9.38@3048.94,897 3048.94,936 ; U9.38@3051.76,931.29 cw(c3054.27,936) 3048.94,936
S_DB0: U6.A3 U9.2 | length 1398
  Top Layer w5: 2236.06,1440.06 cw(c2262.72,1413.4) U6.A3@2262.72,1451.11 ; 2244.6,1448.6 cw(c2262.72,1430.47) U6.A3@2262.72,1456.11 ; 2253.13,1457.13 cw(c2262.72,1447.54) U6.A3@2262.72,1461.11 ; U6.A3@2256.79,1455.18 ccw(c2253.47,1453.9) 2253.47,1457.46 ; U6.A3@2256.79,1459.75 cw(c2253.47,1461.03) 2253.47,1457.46 ; U6.A3@2262.72,1457.46 2253.46,1457.46 ; 2563.07,483.93 cw(c2545.14,466) U9.2@2570.5,466 ; 2571.6,475.4 cw(c2562.21,466) U9.2@2575.5,466 ; U9.2@2576.5,437 2576.5,470.5 2508,539 2456,539 2201,794 2201,1317 ccw(c2196,1317) 2196,1322 2186.41,1322 cw(c2186.41,1327) 2181.41,1327 cw(c2186.41,1327) 2186.41,1332 2196,1332 ccw(c2196,1337) 2201,1337 ccw(c2196,1337) 2196,1342 2186.41,1342 cw(c2186.41,1347) 2181.41,1347 cw(c2186.41,1347) 2186.41,1352 2196,1352 ccw(c2196,1357) 2201,1357 2201,1405 2253.46,1457.46
S_DB1: U6.B3 U9.4 | length 1365.7
  Top Layer w5: U6.B3@2295.74,1457.46 cw(c2280.39,1457.46) 2291.24,1446.61 cw(c2302.09,1435.76) U6.B3@2302.09,1451.11 ; U6.B3@2302.09,1457.46 2283.63,1439 2256,1439 2220,1403 2220,1356 ccw(c2225,1356) 2225,1351 cw(c2225,1346) 2230,1346 cw(c2225,1346) 2225,1341 ccw(c2225,1336) 2220,1336 2220,803 2466,557 2554,557 2639.49,471.51 U9.4@2639.49,437 ; 2625.35,485.65 cw(c2605.7,466) U9.4@2633.49,466 ; 2633.88,477.12 cw(c2622.77,466) U9.4@2638.49,466
S_DB2: U6.A2 U9.5 | length 1362.6
  Top Layer w5: U6.A2@2256.37,1418.09 cw(c2241.02,1418.09) 2251.87,1407.24 cw(c2262.72,1396.39) U6.A2@2262.72,1411.74 ; U6.A2@2262.72,1418.09 2242,1397.37 2242,1318 ccw(c2247,1318) 2247,1313 2255.49,1313 cw(c2255.49,1308) 2260.49,1308 cw(c2255.49,1308) 2255.49,1303 2237,1303 ccw(c2237,1298) 2232,1298 ccw(c2237,1298) 2237,1293 2255.49,1293 cw(c2255.49,1288) 2260.49,1288 cw(c2255.49,1288) 2255.49,1283 2247,1283 ccw(c2247,1278) 2242,1278 2242,809 2473,578 2565.98,578 2670.98,473 U9.5@2670.98,437 ; 2655.79,488.19 cw(c2633.6,466) U9.5@2664.98,466 ; 2664.33,479.66 cw(c2650.67,466) U9.5@2669.98,466
S_DB3: U6.B2 U9.7 | length 1355.8
  Top Layer w5: U6.B2@2295.74,1418.09 cw(c2280.39,1418.09) 2291.24,1407.24 cw(c2302.09,1396.39) U6.B2@2302.09,1411.74 ; U6.B2@2302.09,1418.09 2283,1399 2283,1281 2262,1260 2262,814 2480,596 2608,596 2733.98,470.02 U9.7@2733.98,437 U9.7@2734,472.02 ; 2720.89,483.11 cw(c2703.78,466) U9.7@2727.98,466 ; 2729.42,474.58 cw(c2720.85,466) U9.7@2732.98,466
S_DB4: U6.B1 U9.8 | length 1392.9
  Top Layer w5: U6.B1@2297.6,1374.23 cw(c2286.74,1363.37) 2302.09,1363.37 cw(c2317.44,1363.37) U6.B1@2306.59,1374.23 ; U6.B1@2302.09,1378.72 2302.09,1234 cw(c2297.09,1234) 2297.09,1229 2288.78,1229 ccw(c2288.78,1224) 2283.78,1224 ccw(c2288.78,1224) 2288.78,1219 2297.09,1219 cw(c2297.09,1214) 2302.09,1214 cw(c2297.09,1214) 2297.09,1209 2288.78,1209 ccw(c2288.78,1204) 2283.78,1204 ccw(c2288.78,1204) 2288.78,1199 2297.09,1199 cw(c2297.09,1194) 2302.09,1194 cw(c2297.09,1194) 2297.09,1189 2288.78,1189 ccw(c2288.78,1184) 2283.78,1184 ccw(c2288.78,1184) 2288.78,1179 2297.09,1179 cw(c2297.09,1174) 2302.09,1174 2302.09,800.91 2486,617 2624,617 2765.47,475.53 ; 2748.49,492.51 cw(c2721.99,466) U9.8@2759.47,466 ; 2757.03,483.97 cw(c2739.06,466) U9.8@2764.47,466 ; U9.8@2762.88,471.41 ccw(c2760.91,475.53) 2765.47,475.53 ; U9.8@2765.47,437 2765.47,475.53 ; 2765.56,475.44 cw(c2756.13,466) U9.8@2769.47,466 ; U9.8@2768.06,471.41 cw(c2770.04,475.53) 2765.47,475.53
S_DB5: U6.C2 U9.10 | length 1362.4
  Top Layer w5: U6.C2@2335.11,1418.09 cw(c2319.76,1418.09) 2330.61,1407.24 cw(c2341.46,1396.39) U6.C2@2341.46,1411.74 ; U6.C2@2341.46,1418.09 2321,1397.63 2321,816 2500,637 2665,637 2828.46,473.54 U9.10@2828.46,437 ; 2812.89,489.11 cw(c2789.79,466) U9.10@2822.46,466 ; 2821.43,480.57 cw(c2806.86,466) U9.10@2827.46,466
S_DB6: U6.C1 U9.11 | length 1360
  Top Layer w5: U6.C1@2336.97,1374.23 cw(c2326.11,1363.37) 2341.46,1363.37 cw(c2356.81,1363.37) U6.C1@2345.96,1374.23 ; U6.C1@2341.46,1378.72 2341.46,1194 ccw(c2346.46,1194) 2346.46,1189 2354.31,1189 cw(c2354.31,1184) 2359.31,1184 cw(c2354.31,1184) 2354.31,1179 2346.46,1179 ccw(c2346.46,1174) 2341.46,1174 ccw(c2346.46,1174) 2346.46,1169 2354.31,1169 cw(c2354.31,1164) 2359.31,1164 cw(c2354.31,1164) 2354.31,1159 2346.46,1159 ccw(c2346.46,1154) 2341.46,1154 2341.46,823.54 2506,659 2671,659 2859.99,470.01 U9.11@2859.99,437 ; 2846.92,483.08 cw(c2829.83,466) U9.11@2853.99,466 ; 2855.45,474.55 cw(c2846.9,466) U9.11@2858.99,466
S_DB7: U6.D1 U9.13 | length 1345.5
  Top Layer w5: U6.D1@2376.34,1374.23 cw(c2365.48,1363.37) 2380.83,1363.37 cw(c2396.18,1363.37) U6.D1@2385.33,1374.23 ; U6.D1@2380.83,1378.72 2380.83,1242 cw(c2375.83,1242) 2375.83,1237 2373.36,1237 ccw(c2373.36,1232) 2368.36,1232 ccw(c2373.36,1232) 2373.36,1227 2375.83,1227 cw(c2375.83,1222) 2380.83,1222 2380.83,813.17 2512,682 2710,682 2922.95,469.05 U9.13@2922.95,437 ; 2910.56,481.44 cw(c2895.11,466) U9.13@2916.95,466 ; U9.13@2917.91,474.09 ccw(c2922.95,479.13) U9.13@2922.95,472
S_DB8: U6.H5 U9.42 | length 1641.6
  Top Layer w5: v1@2517.62,1523.95 ccw(c2514.91,1543.93) U6.H5@2532.37,1533.85 ; v1@2518.29,1519 ccw(c2516.64,1531.16) 2527.27,1525.02 ; v1(2518.63,1516.52) U6.H5@2538.32,1536.2 ; v1@2518.63,1524.02 ccw(c2518.63,1542.13) 2531.43,1529.32 ccw(c2544.24,1516.52) v1@2526.13,1516.52 ; v1@2520.6,1523.76 ccw(c2522.41,1530.42) 2528.39,1526.97 ; v1@2521.11,1516.18 cw(c2533.27,1514.53) 2527.13,1525.16 ; v1@2525.87,1518.49 cw(c2532.53,1520.3) 2529.08,1526.28 ; v1@2526.06,1515.51 cw(c2546.04,1512.8) U6.H5@2535.96,1530.26 ; U6.H5@2531.96,1536.2 cw(c2516.61,1536.2) 2527.46,1525.35 cw(c2538.32,1514.5) U6.H5@2538.32,1529.85 ; v1@2917.65,943.74 cw(c2904.85,930.94) 2922.95,930.94 cw(c2941.06,930.94) v1@2928.26,943.74 ; U9.42@2918.71,930.24 ccw(c2908.47,940.49) 2922.95,940.49 ccw(c2937.44,940.49) U9.42@2927.2,930.24 ; v1@2919.52,942.38 cw(c2915.58,934.72) 2923.9,936.95 cw(c2928.42,938.16) v1@2926.32,942.35 ; v1@2919.59,942.35 cw(c2917.48,938.16) 2922.01,936.95 cw(c2930.32,934.72) v1@2926.38,942.38 ; U9.42@2922.95,897 v1(2922.95,949.05) ; v1@2520.57,1523.76 ccw(c2522.4,1530.59) 2525.93,1524.47 cw(c2522.4,1530.59) v1@2520.57,1523.76 ; v1@2525.87,1518.46 cw(c2532.7,1520.29) 2526.58,1523.82 ccw(c2532.7,1520.29) v1@2525.87,1518.46
  Mid-Layer 1 w5: v1@2518.36,1519 cw(c2520.33,1500.85) 2533.24,1513.76 ; v1(2518.63,1516.52) 2530.48,1516.52 ; v1@2518.9,1514.03 cw(c2521.77,1487.54) 2540.62,1506.38 ; v1@2519.44,1509.06 cw(c2523.22,1474.22) 2548,1499 ; v1@2525.41,1513.31 cw(c2530.48,1510.9) 2530.48,1516.52 ; v1@2525.41,1519.73 ccw(c2530.48,1522.13) 2530.48,1516.52 ; v1@2915.45,949.05 ccw(c2897.35,949.05) 2910.15,961.85 ccw(c2922.95,974.65) v1@2922.95,956.55 ; v1(2922.95,949.05) 2878,994 2843,994 2708.57,1128.43 ccw(c2705.03,1124.9) 2701.5,1128.43 2682.48,1109.42 cw(c2678.95,1112.96) 2675.41,1109.42 cw(c2678.95,1112.96) 2675.41,1116.49 2694.42,1135.51 ccw(c2690.89,1139.04) 2694.42,1142.58 ccw(c2690.89,1139.04) 2687.35,1142.58 2668.34,1123.56 cw(c2664.8,1127.1) 2661.27,1123.56 cw(c2664.8,1127.1) 2661.27,1130.63 2680.28,1149.65 ccw(c2676.75,1153.18) 2680.28,1156.72 ccw(c2676.75,1153.18) 2673.21,1156.72 2654.2,1137.71 cw(c2650.66,1141.24) 2647.13,1137.71 cw(c2650.66,1141.24) 2647.13,1144.78 2666.14,1163.79 ccw(c2662.6,1167.32) 2666.14,1170.86 ccw(c2662.6,1167.32) 2659.07,1170.86 2640.06,1151.85 cw(c2636.52,1155.38) 2632.98,1151.85 cw(c2636.52,1155.38) 2632.98,1158.92 2652,1177.93 ccw(c2648.46,1181.47) 2652,1185 ccw(c2648.46,1181.47) 2644.93,1185 2625.91,1165.99 cw(c2622.38,1169.53) 2618.84,1165.99 cw(c2622.38,1169.53) 2618.84,1173.06 2637.86,1192.07 ccw(c2634.32,1195.61) 2637.86,1199.14 ccw(c2634.32,1195.61) 2630.78,1199.14 2611.77,1180.13 cw(c2608.24,1183.67) 2604.7,1180.13 cw(c2608.24,1183.67) 2604.7,1187.2 2623.71,1206.22 ccw(c2620.18,1209.75) 2623.71,1213.29 ccw(c2620.18,1209.75) 2616.64,1213.29 2597.63,1194.27 cw(c2594.09,1197.81) 2590.56,1194.27 cw(c2594.09,1197.81) 2590.56,1201.34 2609.57,1220.36 ccw(c2606.04,1223.89) 2609.57,1227.43 2548,1289 2548,1499 ; 2530.48,1516.52 2548,1499
S_DB9: U6.G5 U9.44 | length 1644.5
  Top Layer w5: v1@2478.25,1523.95 ccw(c2475.54,1543.93) U6.G5@2493,1533.85 ; v1@2478.92,1519 ccw(c2477.27,1531.16) 2487.9,1525.02 ; v1(2479.26,1516.52) U6.G5@2498.94,1536.2 ; v1@2479.26,1524.02 ccw(c2479.26,1542.13) 2492.06,1529.32 ccw(c2504.87,1516.52) v1@2486.76,1516.52 ; v1@2481.23,1523.76 ccw(c2483.04,1530.42) 2489.02,1526.97 ; v1@2481.74,1516.18 cw(c2493.9,1514.53) 2487.76,1525.16 ; v1@2486.5,1518.49 cw(c2493.16,1520.3) 2489.71,1526.28 ; v1@2486.69,1515.51 cw(c2506.67,1512.8) U6.G5@2496.59,1530.26 ; U6.G5@2492.59,1536.2 cw(c2477.24,1536.2) 2488.09,1525.35 cw(c2498.94,1514.5) U6.G5@2498.94,1529.85 ; v1@2854.69,941.7 cw(c2841.89,928.9) 2859.99,928.9 cw(c2878.1,928.9) v1@2865.3,941.7 ; U9.44@2855.75,930.24 ccw(c2845.51,940.49) 2859.99,940.49 ccw(c2874.48,940.49) U9.44@2864.23,930.24 ; v1@2856.87,940.19 cw(c2855.4,936.98) 2858.81,936.07 cw(c2864.2,934.62) v1@2862.4,939.91 ; v1@2857.58,939.91 cw(c2855.79,934.62) 2861.18,936.07 cw(c2864.58,936.98) v1@2863.12,940.19 ; U9.44@2859.99,897 v1(2859.99,947.01) ; v1@2481.2,1523.76 ccw(c2483.03,1530.59) 2486.56,1524.47 cw(c2483.03,1530.59) v1@2481.2,1523.76 ; v1@2486.5,1518.46 cw(c2493.33,1520.29) 2487.21,1523.82 ccw(c2493.33,1520.29) v1@2486.5,1518.46
  Mid-Layer 1 w5: v1@2479.22,1519.02 cw(c2479.49,1500.93) 2492.28,1513.72 ; v1(2479.26,1516.52) 2489.48,1516.52 ; v1@2479.3,1514.02 cw(c2479.73,1484.45) 2500.64,1505.36 ; v1@2479.37,1509.02 cw(c2479.97,1467.98) 2509,1497 ; v1@2486.41,1514.27 cw(c2489.48,1513.3) 2489.48,1516.52 ; v1@2486.41,1518.77 ccw(c2489.48,1519.73) 2489.48,1516.52 ; 2843.65,968.35 cw(c2822.31,947.01) v1@2852.49,947.01 ; 2852.19,959.81 cw(c2839.39,947.01) v1@2857.49,947.01 ; 2855.72,956.28 ccw(c2859.99,960.54) v1@2859.99,954.51 ; v1(2859.99,947.01) 2859.99,952.01 2721,1091 2679,1091 2674.42,1095.58 ccw(c2670.89,1092.04) 2667.35,1095.58 2655.89,1084.11 cw(c2652.36,1087.65) 2648.82,1084.11 cw(c2652.36,1087.65) 2648.82,1091.19 2660.28,1102.65 ccw(c2656.75,1106.18) 2660.28,1109.72 ccw(c2656.75,1106.18) 2653.21,1109.72 2627.61,1084.11 cw(c2624.07,1087.65) 2620.54,1084.11 cw(c2624.07,1087.65) 2620.54,1091.19 2646.14,1116.79 ccw(c2642.6,1120.32) 2646.14,1123.86 ccw(c2642.6,1120.32) 2639.07,1123.86 2615.36,1100.15 cw(c2611.83,1103.69) 2608.29,1100.15 cw(c2611.83,1103.69) 2608.29,1107.22 2632,1130.93 ccw(c2628.46,1134.47) 2632,1138 ccw(c2628.46,1134.47) 2624.93,1138 2601.22,1114.29 cw(c2597.68,1117.83) 2594.15,1114.29 cw(c2597.68,1117.83) 2594.15,1121.37 2617.86,1145.07 ccw(c2614.32,1148.61) 2617.86,1152.14 ccw(c2614.32,1148.61) 2610.78,1152.14 2578.19,1119.55 cw(c2574.65,1123.08) 2571.11,1119.55 cw(c2574.65,1123.08) 2571.11,1126.62 2603.71,1159.22 ccw(c2600.18,1162.75) 2603.71,1166.29 ccw(c2600.18,1162.75) 2596.64,1166.29 2578.19,1147.83 cw(c2574.65,1151.37) 2571.11,1147.83 cw(c2574.65,1151.37) 2571.11,1154.9 2589.57,1173.36 ccw(c2586.04,1176.89) 2589.57,1180.43 2576,1194 2576,1236 2538,1274 2538,1487 2528,1497 2509,1497 ; 2489.48,1516.52 2509,1497
S_DB10: U6.H3 U9.45 | length 1595.3
  Top Layer w5: v1@2517.62,1469.72 cw(c2514.91,1449.74) U6.H3@2532.37,1459.82 ; v1@2518.29,1474.67 cw(c2516.64,1462.51) 2527.27,1468.65 ; v1@2518.63,1469.65 cw(c2518.63,1451.54) 2531.43,1464.35 cw(c2544.24,1477.15) v1@2526.13,1477.15 ; v1(2518.63,1477.15) U6.H3@2538.32,1457.46 ; v1@2520.6,1469.91 cw(c2522.41,1463.24) 2528.4,1466.7 ; v1@2521.11,1477.48 ccw(c2533.27,1479.14) 2527.13,1468.51 ; v1@2526.06,1478.16 ccw(c2546.03,1480.87) U6.H3@2535.96,1463.41 ; 2529.07,1467.39 cw(c2532.52,1473.36) v1@2525.87,1475.18 ; U6.H3@2531.96,1457.46 ccw(c2516.61,1457.46) 2527.46,1468.32 ccw(c2538.32,1479.18) U6.H3@2538.32,1463.82 ; v1@2823.16,944.23 cw(c2810.36,931.43) 2828.46,931.43 cw(c2846.57,931.43) v1@2833.77,944.23 ; U9.45@2824.22,930.24 ccw(c2813.98,940.49) 2828.46,940.49 ccw(c2842.95,940.49) U9.45@2832.71,930.24 ; v1@2824.82,942.98 cw(c2820.21,934.71) 2829.36,937.16 cw(c2834.15,938.45) v1@2831.88,942.86 ; v1@2825.04,942.86 cw(c2822.78,938.45) 2827.57,937.16 cw(c2836.72,934.71) v1@2832.11,942.98 ; U9.45@2828.46,897 v1(2828.46,949.54) ; v1@2525.87,1475.21 ccw(c2532.7,1473.38) 2526.58,1469.84 cw(c2532.7,1473.38) v1@2525.87,1475.21 ; v1@2520.57,1469.9 cw(c2522.4,1463.07) 2525.94,1469.2 ccw(c2522.4,1463.07) v1@2520.57,1469.9
  Mid-Layer 1 w5: v1@2513.33,1471.85 cw(c2487.56,1446.08) 2524,1446.08 ; v1@2516.86,1475.38 cw(c2499.63,1458.15) 2524,1458.15 ; v1(2518.63,1477.15) 2524,1471.78 2524,1267.46 2559,1232.46 2559,1113 2568,1104 ccw(c2571.54,1107.54) 2575.07,1104 2578.53,1107.45 ; 2578.53,1107.45 cw(c2582.06,1103.92) 2585.6,1107.45 cw(c2582.06,1103.92) 2585.6,1100.38 2559.15,1073.94 ccw(c2562.69,1070.4) 2559.15,1066.87 ccw(c2562.69,1070.4) 2566.22,1066.87 2585.68,1086.32 2592.67,1093.31 cw(c2596.2,1089.78) 2599.74,1093.31 cw(c2596.2,1089.78) 2599.74,1086.24 2596.28,1082.79 ccw(c2599.82,1079.25) 2596.28,1075.72 2600,1072 2670,1072 cw(c2670,1067) 2675,1067 2675,1058.78 ccw(c2680,1058.78) 2680,1053.78 ccw(c2680,1058.78) 2685,1058.78 2685,1067 cw(c2690,1067) 2690,1072 2719.46,1072 2725.88,1065.59 cw(c2722.34,1062.05) 2725.88,1058.51 2704.67,1037.3 ccw(c2708.2,1033.77) 2704.67,1030.23 ccw(c2708.2,1033.77) 2711.74,1030.23 2732.95,1051.44 cw(c2736.49,1047.91) 2740.02,1051.44 cw(c2736.49,1047.91) 2740.02,1044.37 2718.81,1023.16 ccw(c2722.34,1019.62) 2718.81,1016.09 ccw(c2722.34,1019.62) 2725.88,1016.09 2747.09,1037.3 cw(c2750.63,1033.77) 2754.16,1037.3 cw(c2750.63,1033.77) 2754.16,1030.23 2732.95,1009.02 ccw(c2736.49,1005.48) 2732.95,1001.95 ccw(c2736.49,1005.48) 2740.02,1001.95 2761.23,1023.16 cw(c2764.77,1019.62) 2768.31,1023.16 cw(c2764.77,1019.62) 2768.31,1016.09 2747.09,994.87 ccw(c2750.63,991.34) 2747.09,987.8 ccw(c2750.63,991.34) 2754.16,987.8 2775.38,1009.02 cw(c2778.91,1005.48) 2782.45,1009.02 cw(c2778.91,1005.48) 2782.45,1001.95 2761.23,980.73 ccw(c2764.77,977.2) 2761.23,973.66 ccw(c2764.77,977.2) 2768.31,973.66 2789.52,994.87 cw(c2793.05,991.34) 2796.59,994.87 2828.46,963 ; v1@2824.52,955.91 ccw(c2820.13,963) 2828.46,963 ; v1(2828.46,949.54) 2828.46,963 ; v1@2832.41,955.91 cw(c2836.8,963) 2828.46,963
S_DB11: U6.F6 U9.47 | length 1558.8
  Top Layer w5: v1@2438.88,1563.32 ccw(c2436.17,1583.3) U6.F6@2453.63,1573.22 ; v1@2439.55,1558.37 ccw(c2437.9,1570.53) 2448.53,1564.39 ; v1(2439.89,1555.89) U6.F6@2459.57,1575.57 ; v1@2439.89,1563.39 ccw(c2439.89,1581.5) 2452.69,1568.69 ccw(c2465.5,1555.89) v1@2447.39,1555.89 ; v1@2442.37,1555.55 cw(c2454.53,1553.9) 2448.39,1564.53 ; v1@2447.32,1554.88 cw(c2467.3,1552.17) U6.F6@2457.22,1569.63 ; 2449.65,1566.34 cw(c2443.67,1569.79) v1@2441.86,1563.13 ; 2450.34,1565.65 ccw(c2453.79,1559.67) v1@2447.13,1557.86 ; U6.F6@2453.22,1575.57 cw(c2437.87,1575.57) 2448.72,1564.72 cw(c2459.57,1553.87) U6.F6@2459.57,1569.22 ; v1@2760.17,946.22 cw(c2747.37,933.42) 2765.47,933.42 cw(c2783.58,933.42) v1@2770.78,946.22 ; U9.47@2761.23,930.24 ccw(c2750.99,940.49) 2765.47,940.49 ccw(c2779.96,940.49) U9.47@2769.72,930.24 ; U9.47@2765.47,897 v1(2765.47,951.53) ; v1@2441.83,1563.13 ccw(c2443.66,1569.96) 2447.19,1563.84 cw(c2443.66,1569.96) v1@2441.83,1563.13 ; v1@2447.13,1557.83 cw(c2453.96,1559.66) 2447.84,1563.19 ccw(c2453.96,1559.66) v1@2447.13,1557.83
  Mid-Layer 1 w5: v1@2439.89,1548.39 cw(c2439.89,1530.28) 2452.69,1543.09 cw(c2465.5,1555.89) v1@2447.39,1555.89 ; v1(2439.89,1555.89) 2459,1536.78 2459,1511 2473,1497 2489,1497 2499,1487 2499,1462 2511,1450 2511,1251 ccw(c2516,1251) 2516,1246 2524.74,1246 cw(c2524.74,1241) 2529.74,1241 cw(c2524.74,1241) 2524.74,1236 2516,1236 ccw(c2516,1231) 2511,1231 ccw(c2516,1231) 2516,1226 2541.49,1226 cw(c2541.49,1221) 2546.49,1221 cw(c2541.49,1221) 2541.49,1216 2516,1216 ccw(c2516,1211) 2511,1211 ccw(c2516,1211) 2516,1206 2541.49,1206 cw(c2541.49,1201) 2546.49,1201 cw(c2541.49,1201) 2541.49,1196 2516,1196 ccw(c2516,1191) 2511,1191 ccw(c2516,1191) 2516,1186 2541.49,1186 cw(c2541.49,1181) 2546.49,1181 cw(c2541.49,1181) 2541.49,1176 2516,1176 ccw(c2516,1171) 2511,1171 ccw(c2516,1171) 2516,1166 2541.49,1166 cw(c2541.49,1161) 2546.49,1161 cw(c2541.49,1161) 2541.49,1156 2516,1156 ccw(c2516,1151) 2511,1151 ccw(c2516,1151) 2516,1146 2541.49,1146 cw(c2541.49,1141) 2546.49,1141 cw(c2541.49,1141) 2541.49,1136 2516,1136 ccw(c2516,1131) 2511,1131 ccw(c2516,1131) 2516,1126 2541.49,1126 cw(c2541.49,1121) 2546.49,1121 cw(c2541.49,1121) 2541.49,1116 2516,1116 ccw(c2516,1111) 2511,1111 2511,1096 2552,1055 2662,1055 v1(2765.47,951.53) ; v1@2757.97,951.53 ccw(c2739.87,951.53) 2752.67,964.33 ccw(c2765.47,977.13) v1@2765.47,959.03
S_DB12: U6.G3 U9.48 | length 1559.7
  Top Layer w5: v1@2478.25,1445.21 ccw(c2475.54,1465.19) U6.G3@2493,1455.11 ; v1@2478.92,1440.26 ccw(c2477.27,1452.42) 2487.9,1446.28 ; v1(2479.26,1437.78) U6.G3@2498.94,1457.46 ; v1@2479.26,1445.28 ccw(c2479.26,1463.39) 2492.06,1450.58 ccw(c2504.87,1437.78) v1@2486.76,1437.78 ; v1@2481.23,1445.02 ccw(c2483.04,1451.68) 2489.02,1448.23 ; v1@2481.74,1437.44 cw(c2493.9,1435.79) 2487.76,1446.42 ; v1@2486.5,1439.75 cw(c2493.16,1441.56) 2489.71,1447.54 ; v1@2486.69,1436.77 cw(c2506.67,1434.06) U6.G3@2496.59,1451.52 ; U6.G3@2492.59,1457.46 cw(c2477.24,1457.46) 2488.09,1446.61 cw(c2498.94,1435.76) U6.G3@2498.94,1451.11 ; v1@2728.67,944.72 cw(c2715.87,931.92) 2733.98,931.92 cw(c2752.08,931.92) v1@2739.28,944.72 ; U9.48@2729.73,930.24 ccw(c2719.49,940.49) 2733.98,940.49 ccw(c2748.46,940.49) U9.48@2738.22,930.24 ; v1@2730.23,943.53 cw(c2725.39,935.15) 2734.74,937.65 ; v1@2730.51,943.37 cw(c2728.08,938.73) 2733.14,937.37 ; 2733.22,937.65 cw(c2742.57,935.15) v1@2737.73,943.53 ; U9.48@2733.98,897 v1(2733.98,950.02) ; 2734.81,937.37 cw(c2739.87,938.73) v1@2737.45,943.37 ; v1@2481.2,1445.02 ccw(c2483.03,1451.85) 2486.56,1445.73 cw(c2483.03,1451.85) v1@2481.2,1445.02 ; v1@2486.5,1439.72 cw(c2493.33,1441.55) 2487.21,1445.08 ccw(c2493.33,1441.55) v1@2486.5,1439.72
  Mid-Layer 1 w5: v1@2479.26,1430.28 cw(c2479.26,1412.17) 2492.06,1424.98 cw(c2504.87,1437.78) v1@2486.76,1437.78 ; v1(2479.26,1437.78) 2498,1419.04 2498,1199 cw(c2493,1199) 2493,1194 2480.63,1194 ccw(c2480.63,1189) 2475.63,1189 ccw(c2480.63,1189) 2480.63,1184 2493,1184 cw(c2493,1179) 2498,1179 cw(c2493,1179) 2493,1174 2480.63,1174 ccw(c2480.63,1169) 2475.63,1169 ccw(c2480.63,1169) 2480.63,1164 2493,1164 cw(c2493,1159) 2498,1159 cw(c2493,1159) 2493,1154 2480.63,1154 ccw(c2480.63,1149) 2475.63,1149 ccw(c2480.63,1149) 2480.63,1144 2493,1144 cw(c2493,1139) 2498,1139 cw(c2493,1139) 2493,1134 2480.63,1134 ccw(c2480.63,1129) 2475.63,1129 ccw(c2480.63,1129) 2480.63,1124 2493,1124 cw(c2493,1119) 2498,1119 2498,1084 2543,1039 2645,1039 2649.12,1034.88 cw(c2645.59,1031.34) 2649.12,1027.81 2631.25,1009.93 ccw(c2634.78,1006.4) 2631.25,1002.86 ccw(c2634.78,1006.4) 2638.32,1002.86 2665.62,1030.16 cw(c2669.16,1026.63) 2672.7,1030.16 cw(c2669.16,1026.63) 2672.7,1023.09 2666.8,1017.2 2645.39,995.79 ccw(c2648.93,992.25) 2645.39,988.72 ccw(c2648.93,992.25) 2652.46,988.72 2673.87,1010.13 2679.77,1016.02 cw(c2683.3,1012.49) 2686.84,1016.02 cw(c2683.3,1012.49) 2686.84,1008.95 2659.53,981.65 ccw(c2663.07,978.11) 2659.53,974.58 ccw(c2663.07,978.11) 2666.6,974.58 2688.01,995.99 2693.91,1001.88 cw(c2697.44,998.34) 2700.98,1001.88 cw(c2697.44,998.34) 2700.98,994.81 2695.09,988.91 2678.36,972.19 ccw(c2681.9,968.66) 2678.36,965.12 ccw(c2681.9,968.66) 2685.44,965.12 2708.05,987.74 cw(c2711.59,984.2) 2715.12,987.74 cw(c2711.59,984.2) 2715.12,980.67 2709.23,974.77 2689.77,955.32 ccw(c2693.31,951.78) 2689.77,948.25 ccw(c2693.31,951.78) 2696.84,948.25 2716.3,967.7 2722.19,973.6 cw(c2725.73,970.06) 2729.26,973.6 cw(c2725.73,970.06) 2729.26,966.52 2726.91,964.17 ccw(c2730.44,960.63) 2726.91,957.09 v1(2733.98,950.02)
S_DB13: U6.F5 U9.50 | length 1645.8
  Top Layer w5: v1@2438.88,1523.95 ccw(c2436.17,1543.93) U6.F5@2453.63,1533.85 ; v1@2439.55,1519 ccw(c2437.9,1531.16) 2448.53,1525.02 ; v1(2439.89,1516.52) U6.F5@2459.57,1536.2 ; v1@2439.89,1524.02 ccw(c2439.89,1542.13) 2452.69,1529.32 ccw(c2465.5,1516.52) v1@2447.39,1516.52 ; v1@2442.37,1516.18 cw(c2454.53,1514.53) 2448.39,1525.16 ; v1@2447.13,1518.49 cw(c2453.79,1520.3) 2450.34,1526.28 ; v1@2447.32,1515.51 cw(c2467.3,1512.8) U6.F5@2457.22,1530.26 ; 2449.65,1526.97 cw(c2443.67,1530.42) v1@2441.86,1523.76 ; U6.F5@2453.22,1536.2 cw(c2437.87,1536.2) 2448.72,1525.35 cw(c2459.57,1514.5) U6.F5@2459.57,1529.85 ; v1@2665.68,943.68 cw(c2652.88,930.88) 2670.98,930.88 cw(c2689.09,930.88) v1@2676.29,943.68 ; U9.50@2666.74,930.24 ccw(c2656.5,940.49) 2670.98,940.49 ccw(c2685.47,940.49) U9.50@2675.23,930.24 ; U9.50@2670.98,897 v1(2670.98,948.98) ; v1@2674.34,942.28 ccw(c2676.43,938.13) 2671.94,936.92 ccw(c2663.73,934.72) 2667.58,942.3 cw(c2665.54,938.13) 2670.03,936.92 cw(c2678.24,934.72) v1@2674.39,942.3 ; v1@2441.83,1523.76 ccw(c2443.66,1530.59) 2447.19,1524.47 cw(c2443.66,1530.59) v1@2441.83,1523.76 ; v1@2447.13,1518.46 cw(c2453.96,1520.29) 2447.84,1523.82 ccw(c2453.96,1520.29) v1@2447.13,1518.46
  Mid-Layer 1 w5: v1@2436.92,1509.63 cw(c2434.96,1505.11) 2439.89,1505.11 ; v1@2437.39,1516.57 ccw(c2457.98,1516.14) 2443.42,1501.58 ; v1(2439.89,1516.52) 2439.89,1505.11 ; v1@2442.39,1516.47 ccw(c2474.22,1515.81) 2451.71,1493.29 ; v1@2442.86,1509.63 ccw(c2444.81,1505.11) 2439.89,1505.11 ; v1@2447.39,1516.36 ccw(c2490.47,1515.47) 2460,1485 ; v1@2663.48,948.98 ccw(c2645.38,948.98) 2658.18,961.79 ccw(c2670.98,974.59) v1@2670.98,956.48 ; v1(2670.98,948.98) 2596.97,1023 2537,1023 2460,1100 2460,1204 ccw(c2455,1204) 2455,1209 cw(c2455,1214) 2450,1214 cw(c2455,1214) 2455,1219 2482.09,1219 ccw(c2482.09,1224) 2487.09,1224 ccw(c2482.09,1224) 2482.09,1229 2455,1229 cw(c2455,1234) 2450,1234 cw(c2455,1234) 2455,1239 2482.09,1239 ccw(c2482.09,1244) 2487.09,1244 ccw(c2482.09,1244) 2482.09,1249 2455,1249 cw(c2455,1254) 2450,1254 cw(c2455,1254) 2455,1259 2482.09,1259 ccw(c2482.09,1264) 2487.09,1264 ccw(c2482.09,1264) 2482.09,1269 2455,1269 cw(c2455,1274) 2450,1274 cw(c2455,1274) 2455,1279 2482.09,1279 ccw(c2482.09,1284) 2487.09,1284 ccw(c2482.09,1284) 2482.09,1289 2455,1289 cw(c2455,1294) 2450,1294 cw(c2455,1294) 2455,1299 2482.09,1299 ccw(c2482.09,1304) 2487.09,1304 ccw(c2482.09,1304) 2482.09,1309 2455,1309 cw(c2455,1314) 2450,1314 cw(c2455,1314) 2455,1319 2482.09,1319 ccw(c2482.09,1324) 2487.09,1324 ccw(c2482.09,1324) 2482.09,1329 2455,1329 cw(c2455,1334) 2450,1334 cw(c2455,1334) 2455,1339 2482.09,1339 ccw(c2482.09,1344) 2487.09,1344 ccw(c2482.09,1344) 2482.09,1349 2455,1349 cw(c2455,1354) 2450,1354 cw(c2455,1354) 2455,1359 2482.09,1359 ccw(c2482.09,1364) 2487.09,1364 ccw(c2482.09,1364) 2482.09,1369 2465,1369 cw(c2465,1374) 2460,1374 2460,1485 ; 2439.89,1505.11 2460,1485
S_DB14: U6.F3 U9.51 | length 1587.3
  Top Layer w5: v1@2438.88,1445.21 ccw(c2436.17,1465.19) U6.F3@2453.63,1455.11 ; v1@2439.55,1440.26 ccw(c2437.9,1452.42) 2448.53,1446.28 ; v1(2439.89,1437.78) U6.F3@2459.57,1457.46 ; v1@2439.89,1445.28 ccw(c2439.89,1463.39) 2452.69,1450.58 ccw(c2465.5,1437.78) v1@2447.39,1437.78 ; v1@2442.37,1437.44 cw(c2454.53,1435.79) 2448.39,1446.42 ; v1@2447.13,1439.75 cw(c2453.79,1441.56) 2450.34,1447.54 ; v1@2447.32,1436.77 cw(c2467.3,1434.06) U6.F3@2457.22,1451.52 ; 2449.65,1448.23 cw(c2443.67,1451.68) v1@2441.86,1445.02 ; U6.F3@2453.22,1457.46 cw(c2437.87,1457.46) 2448.72,1446.61 cw(c2459.57,1435.76) U6.F3@2459.57,1451.11 ; v1@2634.18,944.18 cw(c2621.38,931.38) 2639.49,931.38 cw(c2657.59,931.38) v1@2644.79,944.18 ; U9.51@2635.25,930.24 ccw(c2625,940.49) 2639.49,940.49 ccw(c2653.97,940.49) U9.51@2643.73,930.24 ; v1@2635.86,942.92 cw(c2631.32,934.71) 2640.38,937.14 cw(c2645.15,938.42) v1@2642.9,942.81 ; v1@2636.07,942.81 cw(c2633.83,938.42) 2638.59,937.14 cw(c2647.65,934.71) v1@2643.12,942.92 ; U9.51@2639.49,897 v1(2639.49,949.49) ; v1@2441.83,1445.02 ccw(c2443.66,1451.85) 2447.19,1445.73 cw(c2443.66,1451.85) v1@2441.83,1445.02 ; v1@2447.13,1439.72 cw(c2453.96,1441.55) 2447.84,1445.08 ccw(c2453.96,1441.55) v1@2447.13,1439.72
  Mid-Layer 1 w5: v1@2434.59,1432.48 cw(c2421.78,1419.67) 2439.89,1419.67 cw(c2458,1419.67) v1@2445.19,1432.48 ; v1(2439.89,1437.78) 2439.89,1092.11 2455.07,1076.93 cw(c2451.54,1073.39) 2455.07,1069.86 2432.92,1047.7 ccw(c2436.45,1044.17) 2432.92,1040.63 ccw(c2436.45,1044.17) 2439.99,1040.63 2462.14,1062.79 cw(c2465.68,1059.25) 2469.21,1062.79 cw(c2465.68,1059.25) 2469.21,1055.72 2438.41,1024.91 ccw(c2441.95,1021.38) 2438.41,1017.84 ccw(c2441.95,1021.38) 2445.48,1017.84 2476.28,1048.64 cw(c2479.82,1045.11) 2483.36,1048.64 cw(c2479.82,1045.11) 2483.36,1041.57 2455.8,1014.02 ccw(c2459.34,1010.48) 2455.8,1006.95 ccw(c2459.34,1010.48) 2462.87,1006.95 2490.43,1034.5 cw(c2493.96,1030.97) 2497.5,1034.5 cw(c2493.96,1030.97) 2497.5,1027.43 2469.94,999.88 ccw(c2473.48,996.34) 2469.94,992.81 ccw(c2473.48,996.34) 2477.01,992.81 2504.57,1020.36 cw(c2508.1,1016.82) 2511.64,1020.36 2526.5,1005.5 2536.5,1005.5 cw(c2536.5,1000.5) 2541.5,1000.5 2541.5,976.29 ccw(c2546.5,976.29) 2546.5,971.29 ccw(c2546.5,976.29) 2551.5,976.29 2551.5,1000.5 cw(c2556.5,1000.5) 2556.5,1005.5 cw(c2556.5,1000.5) 2561.5,1000.5 2561.5,971.43 ccw(c2566.5,971.43) 2566.5,966.43 ccw(c2566.5,971.43) 2571.5,971.43 2571.5,1000.5 cw(c2576.5,1000.5) 2576.5,1005.5 2583.48,1005.5 2590.55,998.43 ccw(c2594.08,1001.96) 2597.62,998.43 2597.72,998.53 cw(c2601.26,995) 2604.79,998.53 cw(c2601.26,995) 2604.79,991.46 2601.15,987.82 2586.48,973.15 ccw(c2590.01,969.61) 2586.48,966.08 ccw(c2590.01,969.61) 2593.55,966.08 2608.23,980.75 2611.87,984.39 cw(c2615.4,980.86) 2618.94,984.39 cw(c2615.4,980.86) 2618.94,977.32 2596.7,955.08 ccw(c2600.23,951.54) 2596.7,948.01 ccw(c2600.23,951.54) 2603.77,948.01 2618.83,963.07 cw(c2622.37,959.54) 2625.9,963.07 v1(2639.49,949.49) ; v1@2631.99,949.49 ccw(c2613.88,949.49) 2626.68,962.29 ccw(c2639.49,975.09) v1@2639.49,956.99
